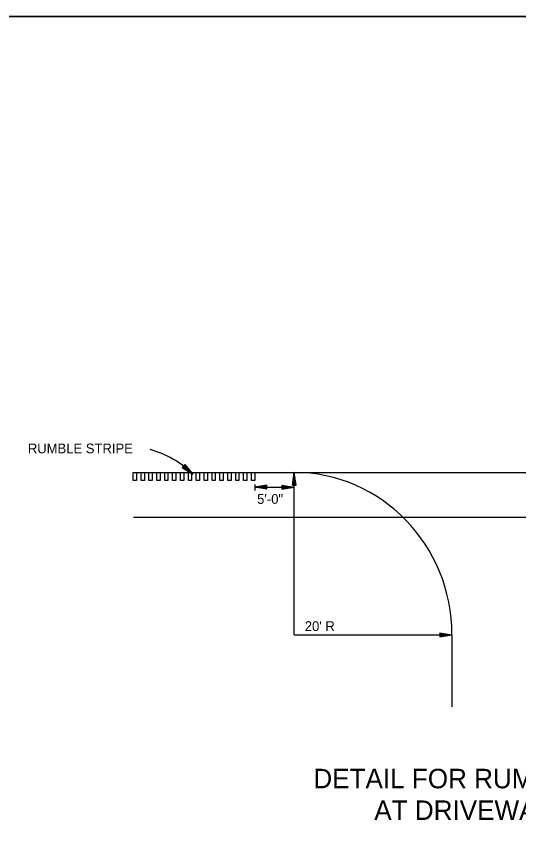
# Model space of a CAD drawing. Extents: x 28704 to 32542, y 50360 to 59122.
# Drawn here: x 29736 to 30070, y 50922 to 51472 of the extents above; entities that cross this region are included whole.
import ezdxf

# ---------------------------------------------------------------- set-up
doc = ezdxf.new("R2010")
doc.units = 0
for name, color, linetype in [('Default', 7, 'Continuous'), ('R_Alt Surface', 7, 'Continuous'), ('R_Alt Surface Annot', 7, 'Continuous')]:
    doc.layers.add(name, color=color, linetype=linetype)

msp = doc.modelspace()

# ---------------------------------------------------------------- linework, layer by layer
at = {"layer": 'Default'}
for points in [[(28703.96, 51472.36), (30403.96, 51472.36), (30403.96, 50372.36), (28703.96, 50372.36)], [(28703.96, 51472.36), (28703.96, 50372.36), (30403.96, 50372.36), (30403.96, 51472.36)]]:
    msp.add_lwpolyline(points, close=True, dxfattribs=at)
at = {"layer": 'R_Alt Surface'}
for p, q in [((29815.67, 51168.75), (30354.46, 51168.75)), ((29920.8, 51060.65), (29920.8, 51168.75)), ((29894.56, 51160.79), (29894.56, 51156.79)), ((29894.56, 51158.93), (29920.8, 51158.93)), ((29813.93, 51138.97), (30352.72, 51138.97)), ((29920.8, 51060.65), (30025.76, 51060.65)), ((30025.76, 51060.65), (30025.76, 51012.79))]:
    msp.add_line(p, q, dxfattribs=at)
for points in [[(29813.67, 51163.39), (29813.67, 51168.8), (29815.85, 51168.8), (29815.85, 51163.39), (29813.67, 51163.39)], [(29818.91, 51163.39), (29818.91, 51168.8), (29821.1, 51168.8), (29821.1, 51163.39), (29818.91, 51163.39)], [(29824.16, 51163.39), (29824.16, 51168.8), (29826.35, 51168.8), (29826.35, 51163.39), (29824.16, 51163.39)], [(29829.41, 51163.39), (29829.41, 51168.8), (29831.59, 51168.8), (29831.59, 51163.39), (29829.41, 51163.39)], [(29834.66, 51163.39), (29834.66, 51168.8), (29836.84, 51168.8), (29836.84, 51163.39), (29834.66, 51163.39)], [(29839.9, 51163.39), (29839.9, 51168.8), (29842.09, 51168.8), (29842.09, 51163.39), (29839.9, 51163.39)], [(29845.15, 51163.39), (29845.15, 51168.8), (29847.34, 51168.8), (29847.34, 51163.39), (29845.15, 51163.39)], [(29850.4, 51163.39), (29850.4, 51168.8), (29852.58, 51168.8), (29852.58, 51163.39), (29850.4, 51163.39)], [(29855.65, 51163.39), (29855.65, 51168.8), (29857.83, 51168.8), (29857.83, 51163.39), (29855.65, 51163.39)], [(29860.89, 51163.39), (29860.89, 51168.8), (29863.08, 51168.8), (29863.08, 51163.39), (29860.89, 51163.39)], [(29866.14, 51163.39), (29866.14, 51168.8), (29868.33, 51168.8), (29868.33, 51163.39), (29866.14, 51163.39)], [(29871.39, 51163.39), (29871.39, 51168.8), (29873.57, 51168.8), (29873.57, 51163.39), (29871.39, 51163.39)], [(29876.64, 51163.39), (29876.64, 51168.8), (29878.82, 51168.8), (29878.82, 51163.39), (29876.64, 51163.39)], [(29881.88, 51163.39), (29881.88, 51168.8), (29884.07, 51168.8), (29884.07, 51163.39), (29881.88, 51163.39)], [(29887.13, 51163.39), (29887.13, 51168.8), (29889.32, 51168.8), (29889.32, 51163.39), (29887.13, 51163.39)], [(29892.38, 51163.39), (29892.38, 51168.8), (29894.56, 51168.8), (29894.56, 51163.39), (29892.38, 51163.39)]]:
    msp.add_lwpolyline(points, dxfattribs=at)
for centre, major_axis, start_param, end_param in [((29808.21, 51118.68), (0, 67.55), 5.523292, 6.026248), ((29920.8, 51060.65), (0, 108.1), 4.712389, 6.283185)]:
    msp.add_ellipse(centre, major_axis=major_axis, ratio=0.970998, start_param=start_param, end_param=end_param, dxfattribs=at)
at = {"layer": 'R_Alt Surface Annot'}
for p, q in [((29847.95, 51173.99), (29846.38, 51172.07)), ((29846.38, 51172.07), (29853.39, 51167.65)), ((29846.51, 51172.23), (29852.35, 51168.55)), ((29846.64, 51172.4), (29851.28, 51169.47)), ((29846.78, 51172.56), (29850.24, 51170.37)), ((29846.91, 51172.72), (29849.19, 51171.28)), ((29847.04, 51172.88), (29848.15, 51172.18)), ((29847.29, 51173.18), (29848.15, 51172.18)), ((29847.42, 51173.34), (29849.19, 51171.28)), ((29847.55, 51173.51), (29850.24, 51170.37)), ((29847.69, 51173.67), (29851.28, 51169.47)), ((29847.82, 51173.83), (29852.35, 51168.55)), ((29847.95, 51173.99), (29853.39, 51167.65)), ((29919.58, 51160.38), (29920.8, 51168.75)), ((29919.58, 51160.38), (29920.8, 51168.75)), ((29919.78, 51160.38), (29920.8, 51167.35)), ((29919.78, 51160.38), (29920.8, 51167.35)), ((29922.02, 51160.38), (29920.8, 51168.75)), ((29922.02, 51160.38), (29920.8, 51168.75)), ((29921.82, 51160.38), (29920.8, 51167.35)), ((29921.82, 51160.38), (29920.8, 51167.35)), ((29919.99, 51160.38), (29920.8, 51165.91)), ((29919.99, 51160.38), (29920.8, 51165.91)), ((29920.19, 51160.38), (29920.8, 51164.52)), ((29920.19, 51160.38), (29920.8, 51164.52)), ((29920.41, 51160.38), (29920.8, 51163.1)), ((29920.41, 51160.38), (29920.8, 51163.1)), ((29920.61, 51160.38), (29920.8, 51161.7)), ((29920.61, 51160.38), (29920.8, 51161.7)), ((29921.61, 51160.38), (29920.8, 51165.91)), ((29921.61, 51160.38), (29920.8, 51165.91)), ((29921.41, 51160.38), (29920.8, 51164.52)), ((29921.41, 51160.38), (29920.8, 51164.52)), ((29921.2, 51160.38), (29920.8, 51163.1)), ((29921.2, 51160.38), (29920.8, 51163.1)), ((29920.99, 51160.38), (29920.8, 51161.7)), ((29920.99, 51160.38), (29920.8, 51161.7)), ((29902.69, 51160.18), (29894.56, 51158.93)), ((29902.69, 51157.67), (29894.56, 51158.93)), ((29902.69, 51159.98), (29895.92, 51158.93)), ((29902.69, 51157.88), (29895.92, 51158.93)), ((29902.69, 51159.76), (29897.32, 51158.93)), ((29902.69, 51158.1), (29897.32, 51158.93)), ((29902.69, 51159.55), (29898.67, 51158.93)), ((29902.69, 51158.31), (29898.67, 51158.93)), ((29902.69, 51159.34), (29900.05, 51158.93)), ((29902.69, 51158.52), (29900.05, 51158.93)), ((29902.69, 51159.13), (29901.41, 51158.93)), ((29902.69, 51158.73), (29901.41, 51158.93)), ((29902.69, 51157.67), (29902.69, 51160.18)), ((29912.67, 51160.18), (29920.8, 51158.93)), ((29912.67, 51160.18), (29912.67, 51157.67)), ((29912.67, 51159.98), (29919.44, 51158.93)), ((29912.67, 51159.76), (29918.05, 51158.93)), ((29912.67, 51159.55), (29916.69, 51158.93)), ((29912.67, 51159.34), (29915.31, 51158.93)), ((29912.67, 51159.13), (29913.96, 51158.93)), ((29912.67, 51157.67), (29920.8, 51158.93)), ((29912.67, 51158.52), (29915.31, 51158.93)), ((29912.67, 51158.1), (29918.05, 51158.93)), ((29912.67, 51157.88), (29919.44, 51158.93)), ((29912.67, 51158.31), (29916.69, 51158.93)), ((29912.67, 51158.73), (29913.96, 51158.93)), ((29919.58, 51160.38), (29922.02, 51160.38)), ((29919.58, 51160.38), (29922.02, 51160.38)), ((30017.63, 51061.91), (30025.76, 51060.65)), ((30017.63, 51061.91), (30017.63, 51059.4)), ((30017.63, 51061.91), (30025.76, 51060.65)), ((30017.63, 51061.91), (30017.63, 51059.4)), ((30017.63, 51061.7), (30024.4, 51060.65)), ((30017.63, 51061.7), (30024.4, 51060.65)), ((30017.63, 51061.49), (30023.01, 51060.65)), ((30017.63, 51061.49), (30023.01, 51060.65)), ((30017.63, 51061.28), (30021.65, 51060.65)), ((30017.63, 51061.28), (30021.65, 51060.65)), ((30017.63, 51061.06), (30020.28, 51060.65)), ((30017.63, 51061.06), (30020.28, 51060.65)), ((30017.63, 51060.85), (30018.92, 51060.65)), ((30017.63, 51060.85), (30018.92, 51060.65)), ((30017.63, 51059.4), (30025.76, 51060.65)), ((30017.63, 51060.24), (30020.28, 51060.65)), ((30017.63, 51059.82), (30023.01, 51060.65)), ((30017.63, 51059.61), (30024.4, 51060.65)), ((30017.63, 51060.03), (30021.65, 51060.65)), ((30017.63, 51060.46), (30018.92, 51060.65)), ((30017.63, 51059.4), (30025.76, 51060.65)), ((30017.63, 51060.24), (30020.28, 51060.65)), ((30017.63, 51059.82), (30023.01, 51060.65)), ((30017.63, 51059.61), (30024.4, 51060.65)), ((30017.63, 51060.03), (30021.65, 51060.65)), ((30017.63, 51060.46), (30018.92, 51060.65))]:
    msp.add_line(p, q, dxfattribs=at)

# ---------------------------------------------------------------- texts
at = {"layer": 'R_Alt Surface'}
for s, height, p in [('RUMBLE STRIPE', 6.485, (29743.61, 51181.51)), ('5\'-0"', 6.485, (29896.15, 51147.85)), ("20' R", 6.485, (29927.86, 51063.18)), ('DETAIL FOR RUMBLE STRIPE GAP', 12.9699, (29933.57, 50958.45)), ('AT DRIVEWAY TURNOUTS', 12.9699, (29974.08, 50937.37))]:
    msp.add_text(s, height=height, dxfattribs=at).set_placement(p)

doc.saveas('drawing.dxf')
